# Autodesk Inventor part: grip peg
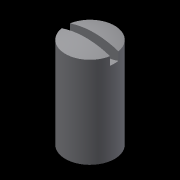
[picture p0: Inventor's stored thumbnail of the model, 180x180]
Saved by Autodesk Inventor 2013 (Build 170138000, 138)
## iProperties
Created: 2013-01
Part Number: grip peg
Material: Generic
Document SubType Name: Modeling
Designer: John
Density: 1 g/cm^3
Author: John
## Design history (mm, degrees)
sketch "Sketch1"
  geometry: L1 (5.08, 9.398)-(5.08, 0); L2 (2.54, 0)-(2.54, 9.819); L3 (2.54, 0)-(5.08, 0); A1 r 7.874 centre (2.54, 1.945) between (5.08, 9.398) and (2.54, 9.819); 1 further point
  constraints: 6 end point, 2 point on circle, 1 centre point, 1 perpendicular
revolve "Revolution1" sketch "Sketch1" stored, may be unused: angle "d3" = 90 deg
sketch "Sketch2"
  geometry: L1 (0, 8.549)-(0, 9.398); L2 (5.08, 9.398)-(5.08, 8.549); A1 r 7.874 centre (2.54, 1.945) between (5.08, 9.398) and (0, 9.398) reference; A2 r 8.077 centre (2.54, 16.216) between (0, 8.549) and (5.08, 8.549); 1 further point
  constraints: 4 end point, 2 point on circle, 1 centre point, 1 parallel, 1 vertical
extrude "Extrusion1" cut sketch "Sketch2" stored distance "d6" = 0.8636; taper "d7" = 0 deg
body "Solid1"
